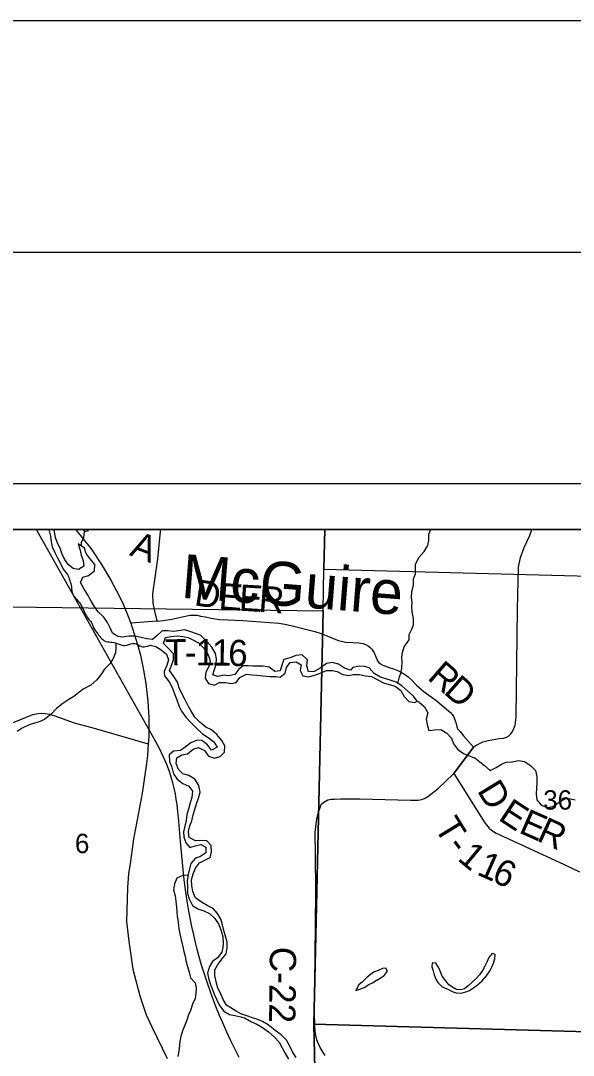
# Model space of a CAD drawing. Extents: x -7.1 to 34, y 0 to 22.
# Drawn here: x 3.24 to 4.434, y 19.764 to 22 of the extents above; entities that cross this region are included whole.
import ezdxf

# ---------------------------------------------------------------- set-up
doc = ezdxf.new("R2010")
doc.units = 0
for name, color, linetype in [('Default', 7, 'Continuous'), ('GM_X_County_Road', 7, 'Continuous'), ('GM_X_County_Road_Text', 7, 'Continuous'), ('GM_X_Major_River', 7, 'Continuous'), ('GM_X_Major_River_Text', 7, 'Continuous'), ('GM_X_Minor_Lake', 7, 'Continuous'), ('GM_X_Minor_River', 7, 'Continuous'), ('GM_X_Rail_Line', 7, 'Continuous'), ('GM_X_Section', 7, 'Continuous'), ('GM_X_Section_Text', 7, 'Continuous'), ('GM_X_State_Route', 7, 'Continuous'), ('GM_X_Township_Road', 7, 'Continuous'), ('GM_X_Township_Road_Text', 7, 'Continuous'), ('SH_Border', 7, 'Continuous'), ('SH_Cut_Line', 7, 'Continuous'), ('SH_Data', 7, 'Continuous')]:
    doc.layers.add(name, color=color, linetype=linetype)

msp = doc.modelspace()

# ---------------------------------------------------------------- linework, layer by layer
at = {"layer": 'Default'}
for points in [[(3.8966, 20.9), (2.8816, 20.9), (2.8771, 20.7376), (3.8931, 20.7247), (3.8945, 20.8149)], [(4.7475, 20.9), (3.8966, 20.9), (3.8945, 20.8149), (4.7431, 20.792)]]:
    msp.add_lwpolyline(points, close=True, dxfattribs=at)
at = {"layer": 'GM_X_County_Road'}
msp.add_line((4.1756, 20.3727), (4.2177, 20.4295), dxfattribs=at)
for points in [[(3.5416, 20.9), (3.5412, 20.8962), (3.5353, 20.837), (3.5242, 20.7609), (3.525, 20.7409), (3.5296, 20.7208), (3.5333, 20.7061)], [(4.2177, 20.4295), (4.2218, 20.4325), (4.227, 20.4357), (4.2323, 20.4384), (4.2381, 20.4411), (4.2495, 20.444), (4.2736, 20.4483), (4.283, 20.4493), (4.2893, 20.4514), (4.2941, 20.4544), (4.2986, 20.4587), (4.3019, 20.4635), (4.3054, 20.4705), (4.3083, 20.4776), (4.31, 20.4949), (4.3128, 20.7284), (4.3154, 20.8189), (4.3196, 20.8398), (4.3276, 20.8616), (4.339, 20.8861), (4.3441, 20.9)], [(3.5333, 20.7061), (3.5343, 20.7022), (3.4779, 20.6975)], [(3.8977, 19.7634), (3.8935, 19.7701), (3.887, 19.7808), (3.8823, 19.7898), (3.8796, 19.7974), (3.8781, 19.8035), (3.876, 19.8154), (3.8749, 19.8286), (3.8748, 19.8551), (3.8769, 20.0448), (3.8771, 20.1181), (3.8767, 20.1969), (3.876, 20.2455), (3.8779, 20.2634), (3.8801, 20.2778), (3.8831, 20.2893), (3.8889, 20.3059), (3.8946, 20.3113), (3.903, 20.3162), (3.9106, 20.3175), (3.918, 20.3176), (3.9307, 20.318), (3.9723, 20.3181), (4.0815, 20.3156), (4.0905, 20.3156), (4.0982, 20.3153), (4.1055, 20.3164), (4.1123, 20.3189), (4.1194, 20.3233), (4.1416, 20.3404), (4.1756, 20.3727)]]:
    msp.add_lwpolyline(points, dxfattribs=at)
at = {"layer": 'GM_X_Major_River'}
for points in [[(3.3007, 20.9), (3.301, 20.8974), (3.3038, 20.8861), (3.3056, 20.8739), (3.308, 20.8626), (3.3132, 20.8509), (3.3195, 20.8393), (3.3254, 20.8269), (3.3316, 20.8148), (3.341, 20.8032)], [(3.5243, 20.6629), (3.5121, 20.6638), (3.4999, 20.667), (3.4865, 20.6695), (3.4744, 20.6697), (3.4599, 20.6679), (3.4496, 20.6692), (3.4381, 20.6763), (3.4322, 20.6894), (3.4275, 20.6992), (3.4193, 20.7105), (3.4069, 20.7224), (3.3988, 20.7344), (3.3917, 20.7457), (3.3843, 20.7596), (3.3764, 20.7731), (3.3686, 20.7855), (3.3741, 20.7973), (3.3862, 20.8009), (3.3994, 20.811), (3.3999, 20.8243), (3.3898, 20.837), (3.3813, 20.8483), (3.3773, 20.8603), (3.3642, 20.8692), (3.3674, 20.8575), (3.3707, 20.8451), (3.3747, 20.833), (3.376, 20.8209), (3.3647, 20.8139), (3.3529, 20.8163), (3.3429, 20.8241), (3.3343, 20.8361), (3.3288, 20.8482), (3.3256, 20.8583), (3.3189, 20.8708), (3.3149, 20.8832), (3.3124, 20.8953), (3.3117, 20.9)], [(3.6294, 20.6711), (3.6198, 20.6751), (3.6076, 20.6791), (3.5946, 20.6834), (3.5703, 20.68), (3.557, 20.6813), (3.5456, 20.6811), (3.5348, 20.671), (3.5243, 20.6629)], [(3.6238, 20.3486), (3.6156, 20.3606), (3.6033, 20.3687), (3.5903, 20.3723), (3.5803, 20.3816), (3.5759, 20.3944), (3.5768, 20.4066), (3.5877, 20.4132), (3.5999, 20.4157), (3.6123, 20.4254), (3.624, 20.4294), (3.6366, 20.4228), (3.6456, 20.4104), (3.6586, 20.4064), (3.6707, 20.4097), (3.68, 20.4193), (3.6805, 20.433), (3.6739, 20.4446), (3.6634, 20.4573), (3.6522, 20.467), (3.64, 20.4729), (3.6269, 20.4837), (3.616, 20.4949), (3.607, 20.5091), (3.6012, 20.5193), (3.5949, 20.5321), (3.5882, 20.5456), (3.5823, 20.5584), (3.5786, 20.5705), (3.5689, 20.5844), (3.5611, 20.5952), (3.5655, 20.6067), (3.5695, 20.6189), (3.5696, 20.6318), (3.5596, 20.6422), (3.548, 20.6542), (3.5523, 20.6668), (3.5641, 20.6689), (3.5777, 20.6706), (3.5903, 20.6693), (3.6017, 20.6668), (3.6113, 20.6621), (3.624, 20.6551), (3.6352, 20.6435), (3.6446, 20.6296), (3.649, 20.6164), (3.6461, 20.6042), (3.6399, 20.5916), (3.6382, 20.5791), (3.6456, 20.5674), (3.6586, 20.5639), (3.6688, 20.5693), (3.6817, 20.5699), (3.6954, 20.5671), (3.7052, 20.5699), (3.7134, 20.5807), (3.7277, 20.5878), (3.7399, 20.5861), (3.7498, 20.5855), (3.7628, 20.5838), (3.7776, 20.5829), (3.7906, 20.5824), (3.8005, 20.581), (3.811, 20.5899), (3.8142, 20.6017), (3.822, 20.6132), (3.8349, 20.6146), (3.8453, 20.6076), (3.8432, 20.5954), (3.8495, 20.5837), (3.8617, 20.582), (3.8749, 20.5853), (3.887, 20.59), (3.9002, 20.5952), (3.9131, 20.5954), (3.9234, 20.5937), (3.9357, 20.5871), (3.9487, 20.585), (3.9581, 20.5867), (3.9718, 20.5869), (3.9844, 20.5841), (3.9973, 20.5828), (4.01, 20.5758), (4.0234, 20.5692), (4.0356, 20.5656), (4.049, 20.5616), (4.061, 20.552), (4.068, 20.5396), (4.0785, 20.5287), (4.0914, 20.5267), (4.0959, 20.5294)], [(3.9519, 20.5964), (3.9393, 20.6004), (3.9266, 20.6093), (3.9132, 20.6129), (3.9007, 20.6108), (3.8868, 20.6003), (3.874, 20.5932), (3.8615, 20.593), (3.8578, 20.6055), (3.8591, 20.6188), (3.8476, 20.6292), (3.8339, 20.6282), (3.8218, 20.6227), (3.8082, 20.6191), (3.8042, 20.6073), (3.8006, 20.5951), (3.7885, 20.5933), (3.7765, 20.6026), (3.7636, 20.6051), (3.7412, 20.6047), (3.7313, 20.6053), (3.7206, 20.6055), (3.7108, 20.5981), (3.7023, 20.5866), (3.6887, 20.5837), (3.6791, 20.5854), (3.6651, 20.5829), (3.6548, 20.5862), (3.6584, 20.598), (3.662, 20.6094), (3.663, 20.6208), (3.6605, 20.6326), (3.6523, 20.6457), (3.6422, 20.658), (3.6287, 20.6711), (3.6294, 20.6711)], [(3.5197, 20.6505), (3.5314, 20.6471), (3.5429, 20.6404), (3.5548, 20.6308), (3.5588, 20.6187), (3.5556, 20.6061), (3.5498, 20.5935), (3.5503, 20.5841), (3.5604, 20.5713), (3.5671, 20.5589), (3.5722, 20.545), (3.5774, 20.5322), (3.5822, 20.5178), (3.5873, 20.508), (3.5966, 20.4949), (3.6079, 20.4822), (3.6198, 20.471), (3.6322, 20.4587), (3.6445, 20.451), (3.6572, 20.4417), (3.6643, 20.4297), (3.6518, 20.4234), (3.6433, 20.4346), (3.6309, 20.4443), (3.621, 20.4449), (3.6075, 20.4393), (3.5951, 20.43), (3.5849, 20.4227), (3.5701, 20.4209), (3.5604, 20.4131), (3.5614, 20.3987), (3.5662, 20.3863), (3.5702, 20.3723), (3.5776, 20.3607), (3.5899, 20.351), (3.6029, 20.3456), (3.6111, 20.3347), (3.6091, 20.321), (3.6062, 20.3092), (3.6023, 20.2962), (3.599, 20.284), (3.597, 20.2711), (3.5945, 20.2589), (3.5917, 20.2467), (3.5922, 20.2361), (3.5963, 20.2229), (3.6052, 20.2132), (3.6169, 20.2168), (3.6286, 20.2193), (3.6394, 20.2138), (3.6396, 20.2013), (3.6279, 20.1939), (3.6173, 20.1903), (3.6073, 20.1787), (3.6044, 20.1669), (3.6012, 20.1543), (3.5995, 20.141), (3.6001, 20.1274), (3.6004, 20.1137), (3.6036, 20.1017), (3.6107, 20.0877), (3.6226, 20.0803), (3.6356, 20.076), (3.6475, 20.0701), (3.6594, 20.0593), (3.668, 20.0466), (3.6728, 20.033), (3.6764, 20.0202), (3.6774, 20.0065), (3.6761, 19.9966), (3.6743, 19.9871), (3.6647, 19.9748), (3.6538, 19.9667), (3.6479, 19.956), (3.6435, 19.9411), (3.6464, 19.9279), (3.6505, 19.9146), (3.6564, 19.9003)], [(4.0959, 20.5294), (4.0885, 20.5403), (4.0758, 20.5507), (4.0634, 20.5623), (4.0508, 20.57), (4.0378, 20.5743), (4.0263, 20.578), (4.0168, 20.5812), (4.0037, 20.5893), (3.9929, 20.6013), (3.9833, 20.6042), (3.9707, 20.6047), (3.9575, 20.6022), (3.9519, 20.5964)], [(4.0959, 20.5294), (4.1005, 20.5272), (4.1121, 20.5168), (4.1195, 20.504), (4.1156, 20.4903), (4.1177, 20.4789), (4.1217, 20.4661), (4.1342, 20.4671), (4.1471, 20.4677), (4.1602, 20.4603), (4.1703, 20.4495), (4.1746, 20.437), (4.1832, 20.4254), (4.1963, 20.4165), (4.2085, 20.4114), (4.2208, 20.4071), (4.2319, 20.3978), (4.2416, 20.3903), (4.2543, 20.3792), (4.2667, 20.3858), (4.2784, 20.3932), (4.2882, 20.3976), (4.3015, 20.3985), (4.3155, 20.401), (4.3281, 20.3986), (4.3408, 20.3905), (4.352, 20.3793), (4.3545, 20.3664), (4.3547, 20.3527), (4.3542, 20.3402), (4.3532, 20.3292), (4.355, 20.316), (4.3643, 20.3044), (4.3777, 20.2993), (4.3909, 20.3025), (4.4029, 20.3107), (4.4157, 20.3192), (4.4279, 20.3179), (4.4374, 20.3162)], [(3.8348, 19.7588), (3.8269, 19.7711), (3.8214, 19.7836), (3.814, 19.7963), (3.8024, 19.8079), (3.7889, 19.8183), (3.7747, 19.8295), (3.762, 19.8368), (3.7497, 19.8419), (3.7402, 19.8452), (3.728, 19.8492), (3.7153, 19.8535), (3.7054, 19.8594), (3.6938, 19.8664), (3.6842, 19.872), (3.6772, 19.8847), (3.672, 19.8968), (3.6658, 19.9088), (3.6617, 19.9224), (3.6588, 19.936), (3.6594, 19.9489), (3.6649, 19.9585), (3.6742, 19.9716), (3.6835, 19.9835), (3.686, 19.996), (3.6861, 20.0082), (3.6825, 20.0214), (3.6789, 20.0335), (3.676, 20.046), (3.672, 20.058), (3.665, 20.0701), (3.6556, 20.0813), (3.6426, 20.0879), (3.6303, 20.0949), (3.6172, 20.1045), (3.6117, 20.1177), (3.6092, 20.131), (3.6086, 20.1431), (3.6122, 20.156), (3.6173, 20.1683), (3.6262, 20.1798), (3.6376, 20.1853), (3.6492, 20.1912), (3.6521, 20.2037), (3.6511, 20.2174), (3.6422, 20.2271), (3.6296, 20.2284), (3.6175, 20.2275), (3.604, 20.2344), (3.6023, 20.2473), (3.6048, 20.2595), (3.6091, 20.2709), (3.612, 20.2835), (3.6156, 20.2953), (3.6192, 20.3075), (3.6239, 20.3194), (3.6271, 20.3323), (3.625, 20.3437), (3.6238, 20.3486)], [(3.6564, 19.9003), (3.6576, 19.8962), (3.6694, 19.8713), (3.6788, 19.859), (3.6906, 19.8523), (3.7025, 19.8499), (3.7154, 19.8471), (3.725, 19.8442), (3.7381, 19.8361), (3.7499, 19.8309), (3.7622, 19.8236), (3.7753, 19.8143), (3.7876, 19.8039), (3.7981, 19.7923), (3.8044, 19.7803), (3.8106, 19.769), (3.8181, 19.7558)]]:
    msp.add_lwpolyline(points, dxfattribs=at)
msp.add_spline([(3.341, 20.8032), (3.3492, 20.7766), (3.3523, 20.7604), (3.3635, 20.746), (3.3716, 20.734), (3.3786, 20.7193), (3.3852, 20.708), (3.3925, 20.6995), (3.3964, 20.6894), (3.4061, 20.6747), (3.4247, 20.658), (3.4375, 20.6568), (3.4549, 20.6514), (3.4693, 20.6502), (3.4863, 20.6541), (3.5007, 20.6471), (3.5119, 20.6479), (3.5197, 20.6505)], degree=3, dxfattribs=at)
at = {"layer": 'GM_X_Minor_Lake'}
msp.add_line((3.3762, 20.9), (3.3773, 20.8961), dxfattribs=at)
for points in [[(3.3773, 20.8961), (3.386, 20.898), (3.3864, 20.9)], [(4.1369, 19.9633), (4.1289, 19.9636), (4.1282, 19.9549), (4.1306, 19.9465), (4.1329, 19.9378), (4.1368, 19.9287), (4.1407, 19.9212), (4.1495, 19.9129), (4.1552, 19.9096), (4.1636, 19.9058), (4.1716, 19.9021), (4.1807, 19.8991), (4.191, 19.8985), (4.2012, 19.9008), (4.2092, 19.9039), (4.2182, 19.9097), (4.2269, 19.9162), (4.2367, 19.925), (4.2457, 19.9354), (4.2525, 19.9449), (4.2577, 19.9544), (4.2615, 19.9632), (4.264, 19.9723), (4.2651, 19.9814), (4.2609, 19.983)], [(4.2609, 19.983), (4.2582, 19.984), (4.2511, 19.9749), (4.2466, 19.965), (4.2425, 19.9562), (4.2373, 19.9471), (4.2309, 19.9379), (4.2234, 19.9299), (4.2151, 19.9218), (4.2064, 19.9138), (4.1985, 19.9076), (4.1902, 19.9053), (4.1814, 19.9064), (4.1727, 19.9112), (4.1646, 19.9165), (4.1581, 19.9251), (4.1504, 19.9349), (4.1465, 19.944), (4.143, 19.9527), (4.1369, 19.9633)], [(4.0296, 19.9505), (4.0287, 19.9521), (4.0211, 19.9517), (4.012, 19.9474), (4.0041, 19.9443), (3.9958, 19.9393), (3.9875, 19.9317), (3.9781, 19.9228), (3.9705, 19.9163), (3.9638, 19.9038)], [(3.9638, 19.9038), (3.9725, 19.9065), (3.9816, 19.9107), (3.9918, 19.9169), (3.9994, 19.9204), (4.0077, 19.9254), (4.016, 19.9308), (4.0251, 19.9365), (4.0322, 19.9457), (4.0296, 19.9505)]]:
    msp.add_lwpolyline(points, dxfattribs=at)
at = {"layer": 'GM_X_Minor_River'}
for points in [[(3.3712, 20.8645), (3.3711, 20.8725), (3.3763, 20.8828), (3.3773, 20.8961), (3.3762, 20.9)], [(4.0545, 20.5677), (4.0581, 20.5821), (4.0618, 20.592), (4.0629, 20.6015), (4.0639, 20.6144), (4.0634, 20.6243), (4.0649, 20.6346), (4.0685, 20.6467), (4.079, 20.6616), (4.0793, 20.673), (4.0838, 20.6837), (4.0886, 20.6943), (4.0881, 20.7076), (4.0853, 20.7227), (4.0845, 20.733), (4.0855, 20.7428), (4.0839, 20.7527), (4.085, 20.7664), (4.0883, 20.7797), (4.0885, 20.7937), (4.0926, 20.8044), (4.0929, 20.8146), (4.0928, 20.8256), (4.1003, 20.8408), (4.1112, 20.8531), (4.1194, 20.8657), (4.1212, 20.8763), (4.1211, 20.89), (4.1258, 20.9)], [(3.4455, 20.6544), (3.4456, 20.6448), (3.4442, 20.6338), (3.439, 20.6197), (3.4323, 20.6097), (3.4206, 20.5983), (3.4142, 20.5887), (3.4045, 20.5757), (3.3909, 20.5642), (3.375, 20.555), (3.3652, 20.5477), (3.3543, 20.5393), (3.3437, 20.5327), (3.3309, 20.5243), (3.3169, 20.5135), (3.3056, 20.5009), (3.2913, 20.4894), (3.2799, 20.4844), (3.2693, 20.4816), (3.258, 20.4781), (3.2428, 20.4712), (3.2319, 20.4639)], [(3.601, 20.153), (3.5902, 20.1525), (3.5769, 20.1467), (3.5717, 20.1348), (3.5699, 20.1216), (3.5734, 20.1083), (3.5751, 20.0973), (3.5763, 20.0837), (3.578, 20.064), (3.5796, 20.0515), (3.5813, 20.0371), (3.5837, 20.0264), (3.5868, 20.0102), (3.59, 19.9984), (3.5924, 19.9882), (3.5947, 19.9784), (3.5963, 19.9685), (3.5999, 19.956), (3.6034, 19.9432), (3.6069, 19.9314), (3.6165, 19.9205), (3.6185, 19.9099), (3.6182, 19.8974), (3.6164, 19.8864), (3.6112, 19.8742), (3.6064, 19.8605), (3.6023, 19.851), (3.5986, 19.8395), (3.5941, 19.8293), (3.5893, 19.8167), (3.5856, 19.8045), (3.5838, 19.7946), (3.5828, 19.7851), (3.5817, 19.7726), (3.5795, 19.7612)]]:
    msp.add_lwpolyline(points, dxfattribs=at)
at = {"layer": 'GM_X_Rail_Line'}
msp.add_lwpolyline([(3.7118, 19.7593), (3.7016, 19.7793), (3.6938, 19.7953), (3.6849, 19.8137), (3.6762, 19.834), (3.6693, 19.8501), (3.6612, 19.8696), (3.6548, 19.8867), (3.6497, 19.9007), (3.6438, 19.9175), (3.6365, 19.9394), (3.6306, 19.959), (3.6256, 19.9768), (3.621, 19.9936), (3.6177, 20.0077), (3.6136, 20.0243), (3.6097, 20.0426), (3.606, 20.0605), (3.6024, 20.0798), (3.5993, 20.0969), (3.5971, 20.1121), (3.595, 20.1271), (3.593, 20.1434), (3.5909, 20.1651), (3.5853, 20.2258), (3.5813, 20.2693), (3.5793, 20.291), (3.5775, 20.3062), (3.5759, 20.3169), (3.5739, 20.3287), (3.5711, 20.3411), (3.5685, 20.3526), (3.5648, 20.365), (3.5609, 20.3773), (3.5553, 20.3922), (3.5485, 20.4085), (3.5398, 20.4268), (3.5311, 20.4429), (3.2978, 20.8577), (3.2788, 20.8909), (3.2736, 20.9)], dxfattribs=at)
at = {"layer": 'GM_X_Section'}
for points in [[(3.8945, 20.8149), (4.7431, 20.792), (4.7229, 19.8074), (3.8731, 19.8315), (3.8931, 20.7247)], [(3.8931, 20.7247), (3.8731, 19.8315), (3.8749, 19.7341), (2.8549, 19.7393), (2.8771, 20.7376)], [(3.8731, 19.8315), (4.7229, 19.8074), (4.6987, 18.8125), (3.8597, 18.828), (3.8749, 19.7341)]]:
    msp.add_lwpolyline(points, close=True, dxfattribs=at)
at = {"layer": 'GM_X_State_Route'}
msp.add_lwpolyline([(3.3581, 20.9), (3.3587, 20.8994), (3.3922, 20.8586), (3.4146, 20.8249), (3.4342, 20.7908), (3.4532, 20.7556), (3.461, 20.7392), (3.4698, 20.7178), (3.4779, 20.6975), (3.4923, 20.6517), (3.4989, 20.6284), (3.5052, 20.5962), (3.5102, 20.5675), (3.5145, 20.5292), (3.5166, 20.4935), (3.5162, 20.4531), (3.5149, 20.4369), (3.514, 20.412), (3.5116, 20.3946), (3.5019, 20.3306), (3.4912, 20.2727), (3.4837, 20.2317), (3.476, 20.178), (3.4728, 20.1565), (3.4704, 20.126), (3.4683, 20.0534), (3.4731, 20.0104), (3.4817, 19.9499), (3.4971, 19.8926), (3.5111, 19.8513), (3.5227, 19.8255), (3.5558, 19.7569)], dxfattribs=at)
at = {"layer": 'GM_X_Township_Road'}
msp.add_line((4.2177, 20.4295), (4.1756, 20.3727), dxfattribs=at)
for points in [[(3.0659, 17.6986), (3.7215, 17.6707), (3.8238, 17.6717), (3.8304, 17.7952), (4.3, 17.7873), (4.5657, 17.7857), (4.7094, 17.7848), (5.0443, 17.7832), (5.0544, 17.7831), (5.1115, 17.7819), (5.5047, 17.7737), (5.7514, 17.7685), (6.1904, 17.7592), (6.3575, 17.7557), (6.7118, 17.7486), (6.7254, 18.1319), (6.7433, 18.7732), (6.7479, 19.0295), (6.7613, 19.7723), (6.7882, 20.743), (6.7921, 20.9), (2.1, 20.9)], [(3.5343, 20.7022), (3.5485, 20.7036), (3.5664, 20.7067), (3.5983, 20.714), (3.6061, 20.7148), (3.6131, 20.715), (3.6208, 20.7148), (3.6284, 20.7133), (3.6392, 20.7112), (3.6512, 20.7087), (3.6695, 20.7058), (3.6874, 20.7048), (3.7193, 20.7033), (3.7973, 20.698), (3.8104, 20.6959), (3.827, 20.692), (3.8493, 20.6863), (3.8753, 20.6795), (3.8887, 20.6754), (3.9171, 20.6641), (3.9262, 20.6604), (3.9416, 20.657), (3.9573, 20.6563), (3.9704, 20.6556), (3.9792, 20.6538), (3.9847, 20.6517), (3.9911, 20.6482), (3.9941, 20.6459), (3.9982, 20.6419), (4.003, 20.634), (4.0089, 20.6204), (4.0107, 20.6163), (4.0136, 20.6126), (4.017, 20.6099), (4.022, 20.6072), (4.0283, 20.6046), (4.0369, 20.6015), (4.0452, 20.5989), (4.0561, 20.5948), (4.0641, 20.5907), (4.0714, 20.586), (4.0768, 20.5818), (4.0832, 20.5759), (4.094, 20.5649), (4.1114, 20.5498), (4.1363, 20.5312), (4.1681, 20.505), (4.1721, 20.5007), (4.1758, 20.4951), (4.1777, 20.4886), (4.1797, 20.4831), (4.1835, 20.4695), (4.189, 20.4634), (4.1961, 20.4541), (4.2177, 20.4295)], [(3.1531, 20.4542), (3.266, 20.5001), (3.2774, 20.5027), (3.2846, 20.5033), (3.2924, 20.5027), (3.302, 20.5009), (3.3136, 20.4973), (3.3556, 20.4825), (3.3937, 20.4721), (3.5149, 20.4369)], [(4.1756, 20.3727), (4.2373, 20.274), (4.2421, 20.2665), (4.2457, 20.2621), (4.2516, 20.2548), (4.2571, 20.2502), (4.2666, 20.2441), (4.4122, 20.1768), (4.447, 20.1604)]]:
    msp.add_lwpolyline(points, dxfattribs=at)
at = {"layer": 'SH_Border'}
msp.add_lwpolyline([(1.5, 21.5), (33.5, 21.5), (33.5, 0.5), (1.5, 0.5)], close=True, dxfattribs=at)
at = {"layer": 'SH_Cut_Line'}
for points in [[(0, 0), (34, 0), (34, 22), (0, 22)], [(8.9, 17.7079), (8.9, 20.9), (2.1, 20.9), (2.1, 17.7253), (2.5551, 17.7155), (2.7886, 17.7105), (3.0659, 17.6986), (3.7215, 17.6707), (3.8238, 17.6717), (3.8304, 17.7952), (4.3, 17.7873), (4.5657, 17.7857), (4.7094, 17.7848), (5.0443, 17.7832), (5.0544, 17.7831), (5.1115, 17.7819), (5.5047, 17.7737), (5.7514, 17.7685), (6.1904, 17.7592), (6.3575, 17.7557), (6.7118, 17.7486), (7.7202, 17.7285), (8.4472, 17.7189), (8.6668, 17.7136)]]:
    msp.add_lwpolyline(points, close=True, dxfattribs=at)
at = {"layer": 'SH_Data'}
for p, q in [((2, 21), (9, 21)), ((2.1, 20.9), (8.9, 20.9))]:
    msp.add_line(p, q, dxfattribs=at)

# ---------------------------------------------------------------- texts
at = {"layer": 'GM_X_County_Road_Text'}
for s, height, rotation, p in [('A', 0.0568, 339.6669, (3.4731, 20.8451)), ('C-22', 0.05682, 269.3129, (3.7782, 19.9986))]:
    msp.add_text(s, height=height, rotation=rotation, dxfattribs=at).set_placement(p)
at = {"layer": 'GM_X_Major_River_Text'}
msp.add_text('McGuire', height=0.09471, rotation=355.4839, dxfattribs=at).set_placement((3.5848, 20.753))
at = {"layer": 'GM_X_Section_Text'}
for s, height, p in [('36', 0.04186, (4.3686, 20.2949)), ('6', 0.0419, (3.3569, 20.2008))]:
    msp.add_text(s, height=height, rotation=0, dxfattribs=at).set_placement(p)
at = {"layer": 'GM_X_Township_Road_Text'}
for s, rotation, p in [('D', 351.466, (3.613, 20.7367)), ('E', 355.0192, (3.6662, 20.7288)), ('E', 356.607, (3.7103, 20.725)), ('R', 355.8885, (3.7525, 20.7225)), ('T', 0.3857, (3.5518, 20.6063)), ('1', 359.7684, (3.6174, 20.6066)), ('1', 359.0711, (3.6523, 20.6065)), ('6', 357.8972, (3.687, 20.6059)), ('-', 0.2342, (3.5942, 20.6065)), ('R', 319.005, (4.1161, 20.5779)), ('D', 318.6989, (4.1513, 20.5473)), ('D', 301.2686, (4.2246, 20.3361)), ('E', 326.7438, (4.2692, 20.274)), ('T', 301.537, (4.1319, 20.2568)), ('E', 336.0812, (4.3135, 20.246)), ('R', 335.3886, (4.3522, 20.2288)), ('-', 307.2158, (4.1576, 20.2155)), ('1', 320.0157, (4.1812, 20.187)), ('1', 336.1542, (4.2228, 20.1553)), ('6', 335.2645, (4.2546, 20.1412))]:
    msp.add_text(s, height=0.0568, rotation=rotation, dxfattribs=at).set_placement(p)

doc.saveas('drawing.dxf')
